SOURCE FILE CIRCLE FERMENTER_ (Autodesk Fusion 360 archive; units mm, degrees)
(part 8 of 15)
sketch "Schizzo1" plane through (-156.8, 0, 0) normal (-1, 0, 0) x axis (0, -1, 0)
  curve K1 (43.7015, -77.2094) -> (43.1419, -79.5252)
  curve K2 (45.0581, -79.5252) -> (44.4985, -77.2094)
  curve K3 (43.7015, 108.1906) -> (43.1419, 105.8748)
  curve K4 (45.0581, 105.8748) -> (44.4985, 108.1906)
  line L1 (65, 103.7507) -> (-65, 103.7507)
  curve K5 (77.2507, 91.5) -> (65, 103.7507)
  line L2 (77.2507, -63.5) -> (77.2507, 91.5)
  curve K6 (65, -75.7507) -> (77.2507, -63.5)
  line L3 (-65, -75.7507) -> (65, -75.7507)
  curve K7 (-77.2507, -63.5) -> (-65, -75.7507)
  line L4 (-77.2507, 91.5) -> (-77.2507, -63.5)
  curve K8 (-65, 103.7507) -> (-77.2507, 91.5)
  line L5 (-65, 111.4507) -> (65, 111.4507)
  curve K9 (-84.9507, 91.5) -> (-65, 111.4507)
  line L6 (-84.9507, -63.5) -> (-84.9507, 91.5)
  curve K10 (-65, -83.4507) -> (-84.9507, -63.5)
  line L7 (65, -83.4507) -> (-65, -83.4507)
  curve K11 (84.9507, -63.5) -> (65, -83.4507)
  line L8 (84.9507, 91.5) -> (84.9507, -63.5)
  curve K12 (65, 111.4507) -> (84.9507, 91.5)
  arc A1 centre (44.1, -78.7) radius 1.2645 clockwise from (45.0581, -79.5252) to (43.1419, -79.5252)
  arc A2 centre (44.1, 106.7) radius 1.2645 clockwise from (45.0581, 105.8748) to (43.1419, 105.8748)
  circle C1 centre (81.5735, 71.5) radius 1.75
  circle C2 centre (81.5735, 71.5) radius 1.75
  circle C3 centre (81.5735, -43.5) radius 1.75
  circle C4 centre (-81.5735, -43.5) radius 1.75
  circle C5 centre (-81.5735, -43.5) radius 1.75
  circle C6 centre (-81.5735, 71.5) radius 1.75
  circle C7 centre (-81.5735, 71.5) radius 1.75
  arc A3 centre (44.1, 106.7) radius 1.543 clockwise from (43.7015, 108.1906) to (44.4985, 108.1906)
  arc A4 centre (44.1, -78.7) radius 1.543 clockwise from (43.7015, -77.2094) to (44.4985, -77.2094)
extrude "Estrusione1" cut sketch "Schizzo1" profile of C1 C2 C3 C4 C5 C6 C7 against normal blind 3 named "d1008_1"
offset_faces "FacceDiOffset1" distance -0.5 named "d1010_1"
sketch "Schizzo2" plane through (0, 0, -63.5) normal (0, 0, -1) x axis (-1, 0, 0)
  line L1 (156.8, -77.2507) -> (156.8, -84.9507)
  line L2 (156.8, 84.9507) -> (156.8, 77.2507)
  line L3 (180, 88.4) -> (160, 88.4)
  line L4 (153.8, 84.9507) -> (156.8, 84.9507)
  curve K1 (160, 86.8) -> (153.8, 85.2507)
  line L5 (160, -86.8) -> (160, -88.4)
  line L6 (160, 88.4) -> (160, 86.8)
  curve K2 (160, 86.55) -> (153.9051, 85.0239)
  line L7 (153.9051, 85.0239) -> (153.8, 84.9507)
  line L8 (160, 88.4) -> (160, 86.55)
  line L9 (156.8, 77.2507) -> (153.8, 77.2507)
  curve K3 (157.8, 77.2507) -> (153.8, 77.2507)
  curve K4 (160.8, 82.6455) -> (157.8, 77.2507)
  curve K5 (164, 88.4) -> (160.8, 82.6455)
  curve K6 (168, 88.4) -> (164, 88.4)
  curve K7 (168, 88.4) -> (153.8, 77.2507)
  line L10 (156.8, 77.2507) -> (153.8, 77.2507)
  line L11 (156.8, 78.3845) -> (156.8, 77.2507)
  point P9 (153.8, 84.9507)
  point P18 (153.8, 84.9507)
  point P6 (160, 88.4)
  point P19 (160, 88.4)
  point P24 (164, 88.4)
  point P25 (168, 88.4)
  point P20 (153.8, 77.2507)
  point P26 (153.8, 77.2507)
  point P21 (156.8, 77.2507)
  point P27 (156.8, 77.2507)
  point P4 (156.8, 77.2507)
  point P28 (156.8, 77.2507)
  point P29 (156.8, 78.3845)
  point P22 (157.8, 77.2507)
  point P23 (160.8, 82.6455)
  coincident P9 P18
  coincident P6 P19
  perpendicular L3 L8
  coincident L3 P24
  coincident L3 P25
  horizontal K3
  parallel K4 K5
  coincident P20 P26
  coincident P21 P27
  coincident P4 P28
  coincident K7 P29
  coincident L2 P29
  dimension "d1011_1" = 0.25
  dimension "d1014_1" distance P20 P22 = 4
  dimension "d1015_1" distance P24 P25 = 4
  dimension "d1016_1" distance P19 P24 = 4
  dimension "d1017_1" distance P22 P24 = 11.1493
  dimension "d1018_1" distance L2 P23 = 4
sweep "Sweep1" sketch "Schizzo2" TwistAngle 0 named "d1023_1" TaperAngle 0 named "d1024_1"
sweep "Sweep2" sketch "Schizzo2" TwistAngle 0 named "d1029_1" TaperAngle 0 named "d1030_1"
remove_body "RimuoviCorpo4"
sketch "Schizzo3" plane through (-160, 0, 0) normal (-1, 0, 0) x axis (0, -1, 0)
  line L1 (-65, 116.5) -> (65, 116.5)
  curve K1 (-65, 116.5) -> (-90, 91.5)
  line L2 (-90, -63.5) -> (-90, 91.5)
  curve K2 (-65, -88.5) -> (-90, -63.5)
  line L3 (65, -88.5) -> (-65, -88.5)
  curve K3 (65, -88.5) -> (90, -63.5)
  line L4 (90, 91.5) -> (90, -63.5)
  curve K4 (65, 116.5) -> (90, 91.5)
  line L5 (65, 114.9) -> (-65, 114.9)
  curve K5 (88.4, 91.5) -> (65, 114.9)
  line L6 (88.4, -63.5) -> (88.4, 91.5)
  curve K6 (88.4, -63.5) -> (65, -86.9)
  line L7 (-65, -86.9) -> (65, -86.9)
  curve K7 (-88.4, -63.5) -> (-65, -86.9)
  line L8 (-88.4, 91.5) -> (-88.4, -63.5)
  curve K8 (-88.4, 91.5) -> (-65, 114.9)
extrude "Estrusione2" add sketch "Schizzo3" along normal blind 20 named "d1031_1"
chamfer "Smusso1" distance 0.8 named "d1033_1"
sketch "Schizzo4" plane through (-148.4, 0, 0) normal (1, 0, 0) x axis (0, 1, 0)
  curve K1 (65, 110.4651) -> (83.9651, 91.5)
  line L1 (-65, 110.4651) -> (65, 110.4651)
  curve K2 (-83.9651, 91.5) -> (-65, 110.4651)
  line L2 (-83.9651, -63.5) -> (-83.9651, 91.5)
  curve K3 (-65, -82.4651) -> (-83.9651, -63.5)
  line L3 (65, -82.4651) -> (-65, -82.4651)
  curve K4 (83.9651, -63.5) -> (65, -82.4651)
  line L4 (83.9651, 91.5) -> (83.9651, -63.5)
  curve K5 (-76.5, -63.5) -> (-65, -75)
  line L5 (-76.5, 91.5) -> (-76.5, -63.5)
  curve K6 (-65, 103) -> (-76.5, 91.5)
  line L6 (65, 103) -> (-65, 103)
  curve K7 (76.5, 91.5) -> (65, 103)
  line L7 (76.5, -63.5) -> (76.5, 91.5)
  curve K8 (65, -75) -> (76.5, -63.5)
  line L8 (-65, -75) -> (65, -75)
  circle C1 centre (-44.1, -78.7) radius 3.35
  circle C2 centre (-44.1, 106.7) radius 3.35
  circle C3 centre (-81.5735, 71.5) radius 1.75
  circle C4 centre (81.5735, 71.5) radius 1.75
  circle C5 centre (-81.5735, -43.5) radius 1.75
  circle C6 centre (81.5735, -43.5) radius 1.75
  circle C7 centre (44.1, 106.7) radius 3.35
  circle C8 centre (44.1, -78.7) radius 3.35
  circle C9 centre (0, -78.7) radius 3.35
  circle C10 centre (-80.2, 14) radius 3.35
  circle C11 centre (0, 106.7) radius 3.35
  circle C12 centre (80.2, 14) radius 3.35
extrude "Estrusione3" cut sketch "Schizzo4" profile of C3 C4 C5 C6 against normal blind 75.727 named "d1034_1"
work_plane "Piano di lavoro1" AlongDistance 3 named "d1036_1"
remove_body "RimuoviCorpo6"
work_plane "Piano di lavoro2" AlongDistance -25 named "d1050_1"
sketch "Schizzo7" plane through (0, 0, -63.5) normal (0, 0, -1) x axis (-1, 0, 0)
  line L1 (180, 88.4) -> (168, 88.4)
  curve K1 (168, 88.4) -> (156.8, 78.3845)
  curve K2 (156.8, 78.3845) -> (153.8, 77.2507)
  line L2 (180, 81.4) -> (180, 88.4)
  curve K3 (177, 81.4) -> (180, 81.4)
  curve K4 (174, 84.9) -> (177, 81.4)
  curve K5 (171, 88.4) -> (174, 84.9)
  curve K6 (168, 88.4) -> (171, 88.4)
  curve K7 (168, 88.4) -> (180, 81.4)
  point P11 (171, 88.4)
  point P3 (180, 88.4)
  point P12 (180, 88.4)
  point P8 (180, 81.4)
  point P9 (177, 81.4)
  point P5 (168, 88.4)
  point P10 (174, 84.9)
  perpendicular L1 L2
  coincident L1 P11
  horizontal K3
  parallel K4 K5
  coincident P3 P12
  dimension "d1051_1" distance P3 P8 = 7
  dimension "d1052_1" distance P8 P9 = 3
  dimension "d1053_1" distance P5 P11 = 3
  dimension "d1054_1" distance P10 K3 = 3.5 (= "d1051_1 / 2")
sketch "Schizzo6" plane through (-180, 0, 0) normal (-1, 0, 0) x axis (0, -1, 0)
  line L1 (65, 114.9) -> (-65, 114.9)
  curve K1 (88.4, 91.5) -> (65, 114.9)
  line L2 (88.4, -63.5) -> (88.4, 91.5)
  curve K2 (65, -86.9) -> (88.4, -63.5)
  line L3 (-65, -86.9) -> (65, -86.9)
  curve K3 (-88.4, -63.5) -> (-65, -86.9)
  line L4 (-88.4, 91.5) -> (-88.4, -63.5)
  curve K4 (-65, 114.9) -> (-88.4, 91.5)
  line L5 (90, 91.5) -> (90, -63.5)
  curve K5 (65, 116.5) -> (90, 91.5)
  line L6 (-65, 116.5) -> (65, 116.5)
  curve K6 (-90, 91.5) -> (-65, 116.5)
  line L7 (-90, -63.5) -> (-90, 91.5)
  curve K7 (-65, -88.5) -> (-90, -63.5)
  line L8 (65, -88.5) -> (-65, -88.5)
  curve K8 (90, -63.5) -> (65, -88.5)
  line L9 (-81.5735, 68.5) -> (-81.5735, 74.5)
  line L10 (-88.4, 60.4309) -> (-79.4522, 69.3787)
  line L11 (-88.4, 82.5691) -> (-79.4522, 73.6213)
  line L12 (-6.0795, 14) -> (-90, 14)
  line L13 (-88.4, -54.5691) -> (-79.4522, -45.6213)
  line L14 (-88.4, -32.4309) -> (-79.4522, -41.3787)
  circle C1 centre (-81.5735, -43.5) radius 1.75
  circle C2 centre (-81.5735, 71.5) radius 1.75
  arc A1 centre (-81.5735, 71.5) radius 3 clockwise from (-79.4522, 73.6213) to (-79.4522, 69.3787)
  arc A2 centre (-81.5735, -43.5) radius 3 clockwise from (-79.4522, -41.3787) to (-79.4522, -45.6213)
  point P20 (-81.5735, 71.5)
  point P24 (-88.4, 60.4309)
  point P26 (-88.4, 82.5691)
  point P27 (-90, 14)
  point P23 (-79.4522, 69.3787)
  point P32 (-79.4522, -41.3787)
  point P33 (-88.4, -32.4309)
  point P25 (-79.4522, 73.6213)
  point P29 (-79.4522, -45.6213)
  point P30 (-88.4, -54.5691)
  concentric C2 A1
  vertical L9
  coincident P20 L9
  coincident L4 P24
  coincident L4 P26
  tangent L11 A1
  tangent L10 A1
  midpoint L7 P27
  perpendicular L4 L12
  symmetric P23 L12 P32
  symmetric P24 L12 P33
  symmetric P25 L12 P29
  symmetric P26 L12 P30
  symmetric A1 L12 A2
  dimension "d1043_1" diameter A1 = 6
  dimension "d1044_1" angle L9 L10 = 135
  dimension "d1045_1" angle L9 L11 = 135
extrude "Estrusione5" add sketch "Schizzo6" profile of L4 C1 C2 A1 L10 L11 L13 A2 L14 to an object
mirror "Specchio1" mirrorStitchTolerance 0.1 named "d1049_1"
sweep "Sweep3" sketch "Schizzo7" TwistAngle 0 named "d1059_1" TaperAngle 0 named "d1060_1"
sketch "Schizzo8" plane through (-153.8, 0, 0) normal (1, 0, 0) x axis (0, 1, 0)
  line L1 (-84.9507, -63.5) -> (-84.9507, 91.5)
  curve K1 (-65, -83.4507) -> (-84.9507, -63.5)
  line L2 (65, -83.4507) -> (-65, -83.4507)
  curve K2 (84.9507, -63.5) -> (65, -83.4507)
  line L3 (84.9507, 91.5) -> (84.9507, -63.5)
  curve K3 (65, 111.4507) -> (84.9507, 91.5)
  line L4 (-65, 111.4507) -> (65, 111.4507)
  curve K4 (-84.9507, 91.5) -> (-65, 111.4507)
  curve K5 (-43.1419, 105.8748) -> (-43.7015, 108.1906)
  curve K6 (-44.4985, 108.1906) -> (-45.0581, 105.8748)
  curve K7 (-43.1419, -79.5252) -> (-43.7015, -77.2094)
  curve K8 (-44.4985, -77.2094) -> (-45.0581, -79.5252)
  line L5 (65, 103.7507) -> (-65, 103.7507)
  curve K9 (65, 103.7507) -> (77.2507, 91.5)
  line L6 (77.2507, -63.5) -> (77.2507, 91.5)
  curve K10 (77.2507, -63.5) -> (65, -75.7507)
  line L7 (-65, -75.7507) -> (65, -75.7507)
  curve K11 (-65, -75.7507) -> (-77.2507, -63.5)
  line L8 (-77.2507, 91.5) -> (-77.2507, -63.5)
  curve K12 (-77.2507, 91.5) -> (-65, 103.7507)
  circle C1 centre (-81.5735, 71.5) radius 2.25
  circle C2 centre (-81.5735, -43.5) radius 2.25
  circle C3 centre (81.5735, 71.5) radius 2.25
  circle C4 centre (81.5735, -43.5) radius 2.25
  arc A1 centre (-44.1, 106.7) radius 1.2645 clockwise from (-43.1419, 105.8748) to (-45.0581, 105.8748)
  arc A2 centre (-44.1, -78.7) radius 1.2645 clockwise from (-43.1419, -79.5252) to (-45.0581, -79.5252)
  circle C5 centre (81.5735, -43.5) radius 1.75
  circle C6 centre (81.5735, 71.5) radius 1.75
  circle C7 centre (-81.5735, 71.5) radius 1.75
  circle C8 centre (-81.5735, 71.5) radius 2.25
  circle C9 centre (-81.5735, -43.5) radius 2.25
  circle C10 centre (-81.5735, -43.5) radius 1.75
  circle C11 centre (81.5735, -43.5) radius 2.25
  circle C12 centre (81.5735, 71.5) radius 2.25
  arc A3 centre (-44.1, 106.7) radius 1.543 clockwise from (-44.4985, 108.1906) to (-43.7015, 108.1906)
  arc A4 centre (-44.1, -78.7) radius 1.543 clockwise from (-44.4985, -77.2094) to (-43.7015, -77.2094)
extrude "Estrusione6" cut sketch "Schizzo8" profile of C5 C6 C7 C10 against normal blind 84.147 named "d1061_1"
extrude "Estrusione7" add sketch "Schizzo8" profile of C1 C2 C3 C4 C5 C6 C7 C8 C9 C10 C11 C12 against normal blind 3.228 named "d1063_1"
fillet "Raccordo1" radius 3 named "d1066_1"
sketch "Schizzo1" plane through (-180, 0, 0) normal (-1, 0, 0) x axis (0, -1, 0)
  line L1 (79.4522, 73.6213) -> (80.5213, 74.6904)
  line L2 (80.5213, 68.3096) -> (79.4522, 69.3787)
  curve K1 (80.5213, 68.3096) -> (81.4, 66.1882)
  line L3 (81.4, -38.1882) -> (81.4, 66.1882)
  curve K2 (81.4, -38.1882) -> (80.5213, -40.3096)
  line L4 (79.4522, -41.3787) -> (80.5213, -40.3096)
  line L5 (80.5213, -46.6904) -> (79.4522, -45.6213)
  curve K3 (80.5213, -46.6904) -> (81.4, -48.8118)
  line L6 (81.4, -63.5) -> (81.4, -48.8118)
  curve K4 (81.4, -63.5) -> (65, -79.9)
  line L7 (-65, -79.9) -> (65, -79.9)
  curve K5 (-65, -79.9) -> (-81.4, -63.5)
  line L8 (-81.4, -48.8118) -> (-81.4, -63.5)
  curve K6 (-81.4, -48.8118) -> (-80.5213, -46.6904)
  line L9 (-79.4522, -45.6213) -> (-80.5213, -46.6904)
  line L10 (-80.5213, -40.3096) -> (-79.4522, -41.3787)
  curve K7 (-80.5213, -40.3096) -> (-81.4, -38.1882)
  line L11 (-81.4, 66.1882) -> (-81.4, -38.1882)
  curve K8 (-81.4, 66.1882) -> (-80.5213, 68.3096)
  line L12 (-79.4522, 69.3787) -> (-80.5213, 68.3096)
  line L13 (-80.5213, 74.6904) -> (-79.4522, 73.6213)
  curve K9 (-80.5213, 74.6904) -> (-81.4, 76.8118)
  line L14 (-81.4, 91.5) -> (-81.4, 76.8118)
  curve K10 (-81.4, 91.5) -> (-65, 107.9)
  line L15 (65, 107.9) -> (-65, 107.9)
  curve K11 (65, 107.9) -> (81.4, 91.5)
  line L16 (81.4, 76.8118) -> (81.4, 91.5)
  curve K12 (81.4, 76.8118) -> (80.5213, 74.6904)
  line L17 (90, 91.5) -> (90, -63.5)
  curve K13 (65, 116.5) -> (90, 91.5)
  line L18 (-65, 116.5) -> (65, 116.5)
  curve K14 (-90, 91.5) -> (-65, 116.5)
  line L19 (-90, -63.5) -> (-90, 91.5)
  curve K15 (-65, -88.5) -> (-90, -63.5)
  line L20 (65, -88.5) -> (-65, -88.5)
  curve K16 (90, -63.5) -> (65, -88.5)
  line L21 (0, -88.5) -> (0, 116.5)
  line L22 (-42.9, -25.4) -> (-42.9, 53.4)
  line L23 (36.4, -31.9) -> (-36.4, -31.9)
  line L24 (42.9, 53.4) -> (42.9, -25.4)
  line L25 (-36.4, 59.9) -> (36.4, 59.9)
  line L26 (65, -86.5) -> (-65, -86.5)
  curve K17 (88, -63.5) -> (65, -86.5)
  line L27 (88, 91.5) -> (88, -63.5)
  curve K18 (65, 114.5) -> (88, 91.5)
  line L28 (-65, 114.5) -> (65, 114.5)
  line L29 (88, 82.1691) -> (80.5213, 74.6904)
  line L30 (88, 60.8309) -> (80.5213, 68.3096)
  line L31 (88, -32.8309) -> (80.5213, -40.3096)
  line L32 (88, -54.1691) -> (80.5213, -46.6904)
  line L33 (-36.4, 59.4) -> (36.4, 59.4)
  line L34 (-42.4, -25.4) -> (-42.4, 53.4)
  line L35 (36.4, -31.4) -> (-36.4, -31.4)
  line L36 (42.4, 53.4) -> (42.4, -25.4)
  arc A1 centre (81.5735, 71.5) radius 3 clockwise from (79.4522, 69.3787) to (79.4522, 73.6213)
  arc A2 centre (81.5735, -43.5) radius 3 clockwise from (79.4522, -45.6213) to (79.4522, -41.3787)
  arc A3 centre (-81.5735, -43.5) radius 3 clockwise from (-79.4522, -41.3787) to (-79.4522, -45.6213)
  arc A4 centre (-81.5735, 71.5) radius 3 clockwise from (-79.4522, 73.6213) to (-79.4522, 69.3787)
  circle C1 centre (81.5735, -43.5) radius 1.75
  circle C2 centre (-81.5735, -43.5) radius 1.75
  circle C3 centre (-81.5735, 71.5) radius 1.75
  circle C4 centre (81.5735, 71.5) radius 1.75
  arc A5 centre (-36.4, -25.4) radius 6.5 clockwise from (-36.4, -31.9) to (-42.9, -25.4)
  arc A6 centre (36.4, -25.4) radius 6.5 clockwise from (42.9, -25.4) to (36.4, -31.9)
  arc A7 centre (36.4, 53.4) radius 6.5 clockwise from (36.4, 59.9) to (42.9, 53.4)
  arc A8 centre (-36.4, 53.4) radius 6.5 clockwise from (-42.9, 53.4) to (-36.4, 59.9)
  arc A9 centre (-36.4, 53.4) radius 6 clockwise from (-42.4, 53.4) to (-36.4, 59.4)
  arc A10 centre (-36.4, -25.4) radius 6 clockwise from (-36.4, -31.4) to (-42.4, -25.4)
  arc A11 centre (36.4, -25.4) radius 6 clockwise from (42.4, -25.4) to (36.4, -31.4)
  arc A12 centre (36.4, 53.4) radius 6 clockwise from (36.4, 59.4) to (42.4, 53.4)
  point P46 (0, 116.5)
  point P47 (0, -88.5)
  point P2 (80.5213, 74.6904)
  point P66 (80.5213, 74.6904)
  point P67 (88, 82.1691)
  point P6 (80.5213, 68.3096)
  point P68 (80.5213, 68.3096)
  point P69 (88, 60.8309)
  point P9 (80.5213, -40.3096)
  point P70 (80.5213, -40.3096)
  point P71 (88, -32.8309)
  point P13 (80.5213, -46.6904)
  point P72 (80.5213, -46.6904)
  point P73 (88, -54.1691)
  midpoint L18 P46
  midpoint L20 P47
  coincident P2 P66
  coincident L27 P67
  coincident P6 P68
  coincident L27 P69
  coincident P9 P70
  coincident L27 P71
  coincident P13 P72
  coincident L27 P73
  tangent L22 A5
  tangent L22 A8
  tangent A6 L24
  tangent A5 L23
  tangent L23 A6
  tangent A7 L25
  tangent L24 A7
  tangent L25 A8
  dimension "d1068_1" = -2
extrude "Estrusione1" new body sketch "Schizzo1" profile of L1 A1 L2 L4 A2 L5 L21 L24 L23 A6 A7 L25 K17 L26 L27 K18 L28 L29 L30 L31 L32 along normal blind 3 named "d1069_1"
fillet "Raccordo1" radius 5 named "d1072_1"
sketch "Schizzo2" plane through (-183, 0, 0) normal (-1, 0, 0) x axis (0, -1, 0)
  line L1 (79.4522, -45.6213) -> (86.5355, -52.7047)
  line L2 (86.5355, -34.2953) -> (79.4522, -41.3787)
  line L3 (88, 58.7598) -> (88, -30.7598)
  line L4 (79.4522, 69.3787) -> (86.5355, 62.2953)
  line L5 (86.5355, 80.7047) -> (79.4522, 73.6213)
  line L6 (88, 91.5) -> (88, 84.2402)
  curve K1 (65, 114.5) -> (88, 91.5)
  line L7 (0, 114.5) -> (65, 114.5)
  line L8 (0, 59.9) -> (0, 114.5)
  line L9 (36.4, 59.9) -> (0, 59.9)
  line L10 (42.9, -25.4) -> (42.9, 53.4)
  line L11 (0, -31.9) -> (36.4, -31.9)
  line L12 (0, -86.5) -> (0, -31.9)
  line L13 (65, -86.5) -> (0, -86.5)
  curve K2 (88, -63.5) -> (65, -86.5)
  line L14 (88, -56.2402) -> (88, -63.5)
  line L15 (79.4522, 73.6213) -> (80.5213, 74.6904)
  line L16 (80.5213, 68.3096) -> (79.4522, 69.3787)
  curve K3 (80.5213, 68.3096) -> (81.4, 66.1882)
  line L17 (81.4, -38.1882) -> (81.4, 66.1882)
  curve K4 (81.4, -38.1882) -> (80.5213, -40.3096)
  line L18 (79.4522, -41.3787) -> (80.5213, -40.3096)
  line L19 (80.5213, -46.6904) -> (79.4522, -45.6213)
  curve K5 (80.5213, -46.6904) -> (81.4, -48.8118)
  line L20 (81.4, -63.5) -> (81.4, -48.8118)
  curve K6 (81.4, -63.5) -> (65, -79.9)
  line L21 (-65, -79.9) -> (65, -79.9)
  curve K7 (-65, -79.9) -> (-81.4, -63.5)
  line L22 (-81.4, -48.8118) -> (-81.4, -63.5)
  curve K8 (-81.4, -48.8118) -> (-80.5213, -46.6904)
  line L23 (-79.4522, -45.6213) -> (-80.5213, -46.6904)
  line L24 (-80.5213, -40.3096) -> (-79.4522, -41.3787)
  curve K9 (-80.5213, -40.3096) -> (-81.4, -38.1882)
  line L25 (-81.4, 66.1882) -> (-81.4, -38.1882)
  curve K10 (-81.4, 66.1882) -> (-80.5213, 68.3096)
  line L26 (-79.4522, 69.3787) -> (-80.5213, 68.3096)
  line L27 (-80.5213, 74.6904) -> (-79.4522, 73.6213)
  curve K11 (-80.5213, 74.6904) -> (-81.4, 76.8118)
  line L28 (-81.4, 91.5) -> (-81.4, 76.8118)
  curve K12 (-81.4, 91.5) -> (-65, 107.9)
  line L29 (65, 107.9) -> (-65, 107.9)
  curve K13 (65, 107.9) -> (81.4, 91.5)
  line L30 (81.4, 76.8118) -> (81.4, 91.5)
  curve K14 (81.4, 76.8118) -> (80.5213, 74.6904)
  line L31 (90, 91.5) -> (90, -63.5)
  curve K15 (65, 116.5) -> (90, 91.5)
  line L32 (-65, 116.5) -> (65, 116.5)
  curve K16 (-90, 91.5) -> (-65, 116.5)
  line L33 (-90, -63.5) -> (-90, 91.5)
  curve K17 (-65, -88.5) -> (-90, -63.5)
  line L34 (65, -88.5) -> (-65, -88.5)
  curve K18 (90, -63.5) -> (65, -88.5)
  curve K19 (65, 110.9) -> (84.4, 91.5)
  line L35 (65, 110.9) -> (-65, 110.9)
  curve K20 (-84.4, 91.5) -> (-65, 110.9)
  line L36 (-84.4, 91.5) -> (-84.4, 76.8118)
  curve K21 (-82.6426, 72.5691) -> (-84.4, 76.8118)
  line L37 (-82.6426, 72.5691) -> (-81.5735, 71.5)
  line L38 (-81.5735, 71.5) -> (-82.6426, 70.4309)
  curve K22 (-84.4, 66.1882) -> (-82.6426, 70.4309)
  line L39 (-84.4, 66.1882) -> (-84.4, -38.1882)
  curve K23 (-82.6426, -42.4309) -> (-84.4, -38.1882)
  line L40 (-82.6426, -42.4309) -> (-81.5735, -43.5)
  line L41 (-81.5735, -43.5) -> (-82.6426, -44.5691)
  curve K24 (-84.4, -48.8118) -> (-82.6426, -44.5691)
  line L42 (-84.4, -48.8118) -> (-84.4, -63.5)
  curve K25 (-65, -82.9) -> (-84.4, -63.5)
  line L43 (-65, -82.9) -> (65, -82.9)
  curve K26 (84.4, -63.5) -> (65, -82.9)
  line L44 (84.4, -63.5) -> (84.4, -48.8118)
  curve K27 (82.6426, -44.5691) -> (84.4, -48.8118)
  line L45 (82.6426, -44.5691) -> (81.5735, -43.5)
  line L46 (81.5735, -43.5) -> (82.6426, -42.4309)
  curve K28 (84.4, -38.1882) -> (82.6426, -42.4309)
  line L47 (84.4, -38.1882) -> (84.4, 66.1882)
  curve K29 (82.6426, 70.4309) -> (84.4, 66.1882)
  line L48 (82.6426, 70.4309) -> (81.5735, 71.5)
  line L49 (81.5735, 71.5) -> (82.6426, 72.5691)
  curve K30 (84.4, 76.8118) -> (82.6426, 72.5691)
  line L50 (84.4, 76.8118) -> (84.4, 91.5)
  line L51 (-106.4199, 14) -> (88, 14)
  arc A1 centre (83, -56.2402) radius 5 clockwise from (86.5355, -52.7047) to (88, -56.2402)
  arc A2 centre (81.5735, -43.5) radius 3 clockwise from (79.4522, -45.6213) to (79.4522, -41.3787)
  arc A3 centre (83, -30.7598) radius 5 clockwise from (88, -30.7598) to (86.5355, -34.2953)
  arc A4 centre (83, 58.7598) radius 5 clockwise from (86.5355, 62.2953) to (88, 58.7598)
  arc A5 centre (81.5735, 71.5) radius 3 clockwise from (79.4522, 69.3787) to (79.4522, 73.6213)
  arc A6 centre (83, 84.2402) radius 5 clockwise from (88, 84.2402) to (86.5355, 80.7047)
  arc A7 centre (36.4, 53.4) radius 6.5 clockwise from (36.4, 59.9) to (42.9, 53.4)
  arc A8 centre (36.4, -25.4) radius 6.5 clockwise from (42.9, -25.4) to (36.4, -31.9)
  arc A9 centre (81.5735, 71.5) radius 3 clockwise from (79.4522, 69.3787) to (79.4522, 73.6213)
  arc A10 centre (81.5735, -43.5) radius 3 clockwise from (79.4522, -45.6213) to (79.4522, -41.3787)
  arc A11 centre (-81.5735, -43.5) radius 3 clockwise from (-79.4522, -41.3787) to (-79.4522, -45.6213)
  arc A12 centre (-81.5735, 71.5) radius 3 clockwise from (-79.4522, 73.6213) to (-79.4522, 69.3787)
  circle C1 centre (81.5735, -43.5) radius 1.75
  circle C2 centre (-81.5735, -43.5) radius 1.75
  circle C3 centre (-81.5735, 71.5) radius 1.75
  circle C4 centre (81.5735, 71.5) radius 1.75
  point P106 (25, 110.9)
  point P107 (84.4, 39)
  point P108 (88, 14)
  point P110 (25, -82.9)
  point P111 (84.4, -11)
  coincident L35 P106
  coincident L47 P107
  midpoint L3 P108
  perpendicular L47 L51
  symmetric P106 L51 P110
  symmetric P107 L51 P111
  dimension "d1073_1" = -3
  dimension "d1074_1" = 50
  dimension "d1075_1" distance L8 P106 = 25
hole "Foratura1" HoleDepth 12.597 named "d1076_1" HoleDiameter 3.5 named "d1077_1" TipAngle 180 named "d1078_1"
mirror "Specchio1" mirrorStitchTolerance 0.1 named "d1083_1"
sketch "Schizzo9" plane through (-183, 0, 0) normal (-1, 0, 0) x axis (0, -1, 0)
  line L1 (65, -86.5) -> (-65, -86.5)
  curve K1 (88, -63.5) -> (65, -86.5)
  line L2 (88, -56.2402) -> (88, -63.5)
  line L3 (79.4522, -45.6213) -> (86.5355, -52.7047)
  line L4 (86.5355, -34.2953) -> (79.4522, -41.3787)
  line L5 (88, 58.7598) -> (88, -30.7598)
  line L6 (79.4522, 69.3787) -> (86.5355, 62.2953)
  line L7 (86.5355, 80.7047) -> (79.4522, 73.6213)
  line L8 (88, 91.5) -> (88, 84.2402)
  curve K2 (65, 114.5) -> (88, 91.5)
  line L9 (-65, 114.5) -> (65, 114.5)
  curve K3 (-65, 114.5) -> (-88, 91.5)
  line L10 (-88, 84.2402) -> (-88, 91.5)
  line L11 (-79.4522, 73.6213) -> (-86.5355, 80.7047)
  line L12 (-86.5355, 62.2953) -> (-79.4522, 69.3787)
  line L13 (-88, -30.7598) -> (-88, 58.7598)
  line L14 (-79.4522, -41.3787) -> (-86.5355, -34.2953)
  line L15 (-86.5355, -52.7047) -> (-79.4522, -45.6213)
  line L16 (-88, -63.5) -> (-88, -56.2402)
  curve K4 (-88, -63.5) -> (-65, -86.5)
  line L17 (-36.4, -31.9) -> (36.4, -31.9)
  line L18 (-42.9, 53.4) -> (-42.9, -25.4)
  line L19 (36.4, 59.9) -> (-36.4, 59.9)
  line L20 (42.9, -25.4) -> (42.9, 53.4)
  arc A1 centre (83, -56.2402) radius 5 clockwise from (86.5355, -52.7047) to (88, -56.2402)
  arc A2 centre (81.5735, -43.5) radius 3 clockwise from (79.4522, -45.6213) to (79.4522, -41.3787)
  arc A3 centre (83, -30.7598) radius 5 clockwise from (88, -30.7598) to (86.5355, -34.2953)
  arc A4 centre (83, 58.7598) radius 5 clockwise from (86.5355, 62.2953) to (88, 58.7598)
  arc A5 centre (81.5735, 71.5) radius 3 clockwise from (79.4522, 69.3787) to (79.4522, 73.6213)
  arc A6 centre (83, 84.2402) radius 5 clockwise from (88, 84.2402) to (86.5355, 80.7047)
  arc A7 centre (-83, 84.2402) radius 5 clockwise from (-86.5355, 80.7047) to (-88, 84.2402)
  arc A8 centre (-81.5735, 71.5) radius 3 clockwise from (-79.4522, 73.6213) to (-79.4522, 69.3787)
  arc A9 centre (-83, 58.7598) radius 5 clockwise from (-88, 58.7598) to (-86.5355, 62.2953)
  arc A10 centre (-83, -30.7598) radius 5 clockwise from (-86.5355, -34.2953) to (-88, -30.7598)
  arc A11 centre (-81.5735, -43.5) radius 3 clockwise from (-79.4522, -41.3787) to (-79.4522, -45.6213)
  arc A12 centre (-83, -56.2402) radius 5 clockwise from (-88, -56.2402) to (-86.5355, -52.7047)
  circle C1 centre (-25, 110.9) radius 1.75
  circle C2 centre (-84.4, -11) radius 1.75
  circle C3 centre (-25, -82.9) radius 1.75
  circle C4 centre (-84.4, 39) radius 1.75
  circle C5 centre (84.4, 39) radius 1.75
  circle C6 centre (25, -82.9) radius 1.75
  circle C7 centre (84.4, -11) radius 1.75
  circle C8 centre (25, 110.9) radius 1.75
  arc A13 centre (-36.4, -25.4) radius 6.5 clockwise from (-36.4, -31.9) to (-42.9, -25.4)
  arc A14 centre (-36.4, 53.4) radius 6.5 clockwise from (-42.9, 53.4) to (-36.4, 59.9)
  arc A15 centre (36.4, 53.4) radius 6.5 clockwise from (36.4, 59.9) to (42.9, 53.4)
  arc A16 centre (36.4, -25.4) radius 6.5 clockwise from (42.9, -25.4) to (36.4, -31.9)
extrude "Estrusione8" cut sketch "Schizzo9" profile of C1 C2 C4 against normal blind 11.8105 named "d1084_1"
sketch "Schizzo7" plane through (-153.8, 0, 0) normal (-1, 0, 0) x axis (0, -1, 0)
  line L1 (20, 10.5) -> (-20, 10.5)
  line L2 (-20, -28.5) -> (20, -28.5)
  line L3 (-20, 22.5) -> (20, 22.5)
  line L4 (20, 47.5) -> (-20, 47.5)
  line L5 (-83.1107, -63.5) -> (-83.1107, -45.4967)
  curve K1 (-65, -81.6107) -> (-83.1107, -63.5)
  line L6 (65, -81.6107) -> (-65, -81.6107)
  curve K2 (83.1107, -63.5) -> (65, -81.6107)
  line L7 (83.1107, -45.4967) -> (83.1107, -63.5)
  line L8 (83.1107, 69.5033) -> (83.1107, -41.5033)
  line L9 (83.1107, 91.5) -> (83.1107, 73.4967)
  curve K3 (65, 109.6107) -> (83.1107, 91.5)
  line L10 (-65, 109.6107) -> (65, 109.6107)
  curve K4 (-83.1107, 91.5) -> (-65, 109.6107)
  line L11 (-83.1107, 73.4967) -> (-83.1107, 91.5)
  line L12 (-83.1107, -41.5033) -> (-83.1107, 69.5033)
  line L13 (0, 121.3204) -> (0, 47.5)
  line L14 (10.25, -63.8607) -> (-10.25, -63.8607)
  line L15 (10.25, -49.3607) -> (10.25, -63.8607)
  line L16 (-10.25, -49.3607) -> (10.25, -49.3607)
  line L17 (-10.25, -63.8607) -> (-10.25, -49.3607)
  line L18 (10.25, -49.3607) -> (-10.25, -63.8607)
  line L19 (-10.25, -49.3607) -> (10.25, -63.8607)
  arc A1 centre (-20, 35) radius 12.5 clockwise from (-20, 22.5) to (-20, 47.5)
  arc A2 centre (20, 35) radius 12.5 clockwise from (20, 47.5) to (20, 22.5)
  circle C1 centre (44.1, -78.7) radius 1.75
  circle C2 centre (44.1, 106.7) radius 1.75
  arc A3 centre (-82.6107, -41.5033) radius 0.5 clockwise from (-82.3802, -41.947) to (-83.1107, -41.5033)
  arc A4 centre (-81.5735, -43.5) radius 1.75 clockwise from (-82.3802, -41.947) to (-82.3802, -45.053)
  arc A5 centre (-82.6107, -45.4967) radius 0.5 clockwise from (-83.1107, -45.4967) to (-82.3802, -45.053)
  arc A6 centre (82.6107, -45.4967) radius 0.5 clockwise from (82.3802, -45.053) to (83.1107, -45.4967)
  arc A7 centre (81.5735, -43.5) radius 1.75 clockwise from (82.3802, -45.053) to (82.3802, -41.947)
  arc A8 centre (82.6107, -41.5033) radius 0.5 clockwise from (83.1107, -41.5033) to (82.3802, -41.947)
  arc A9 centre (82.6107, 69.5033) radius 0.5 clockwise from (82.3802, 69.947) to (83.1107, 69.5033)
  arc A10 centre (81.5735, 71.5) radius 1.75 clockwise from (82.3802, 69.947) to (82.3802, 73.053)
  arc A11 centre (82.6107, 73.4967) radius 0.5 clockwise from (83.1107, 73.4967) to (82.3802, 73.053)
  arc A12 centre (-82.6107, 73.4967) radius 0.5 clockwise from (-82.3802, 73.053) to (-83.1107, 73.4967)
  arc A13 centre (-81.5735, 71.5) radius 1.75 clockwise from (-82.3802, 73.053) to (-82.3802, 69.947)
  arc A14 centre (-82.6107, 69.5033) radius 0.5 clockwise from (-83.1107, 69.5033) to (-82.3802, 69.947)
  arc A15 centre (-20, -9) radius 19.5 clockwise from (-20, -28.5) to (-20, 10.5)
  arc A16 centre (20, -9) radius 19.5 clockwise from (20, 10.5) to (20, -28.5)
  circle C3 centre (-44.1, 106.7) radius 1.75
  circle C4 centre (-44.1, -78.7) radius 1.75
  circle C5 centre (0, -78.7) radius 1.75
  circle C6 centre (80.2, 14) radius 1.75
  circle C7 centre (0, 106.7) radius 1.75
  circle C8 centre (-80.2, 14) radius 1.75
  point P50 (0, 47.5)
  point P56 (0, -56.6107)
  point P54 (10.25, -49.3607)
  point P55 (-10.25, -49.3607)
  point P53 (10.25, -63.8607)
  midpoint L4 P50
  horizontal L14
  perpendicular L14 L15
  parallel L14 L16
  parallel L15 L17
  coincident L18 P56
  coincident L19 P56
  coincident L13 P56
  vertical L13
  dimension "d1086_1" distance P54 P55 = 20.5
  dimension "d1087_1" distance P53 P54 = 14.5
  dimension "d1102_1" distance L6 P56 = 25
extrude "Estrusione2" cut sketch "Schizzo7" profile of L14 L15 L16 L17 against normal blind 7.886 named "d1089_1"
component_insert "Inserimento componente2"
joint "Assembla4" alignAngle 0 named "d1095_1" alignOffsetX 0 named "d1096_1" alignOffsetY 0 named "d1097_1" alignOffsetZ 0.25 named "d1098_1"
sketch "Schizzo8" plane through (-153.8, 0, 0) normal (-1, 0, 0) x axis (0, -1, 0)
  line L1 (-10.25, -63.8607) -> (10.25, -63.8607)
  line L2 (10.25, -49.3607) -> (-10.25, -49.3607)
  line L3 (10.25, -63.8607) -> (10.25, -49.3607)
  line L4 (20, 10.5) -> (-20, 10.5)
  line L5 (-20, -28.5) -> (20, -28.5)
  line L6 (-20, 22.5) -> (20, 22.5)
  line L7 (20, 47.5) -> (-20, 47.5)
  line L8 (-83.1107, -63.5) -> (-83.1107, -45.4967)
  curve K1 (-65, -81.6107) -> (-83.1107, -63.5)
  line L9 (65, -81.6107) -> (-65, -81.6107)
  curve K2 (83.1107, -63.5) -> (65, -81.6107)
  line L10 (83.1107, -45.4967) -> (83.1107, -63.5)
  line L11 (83.1107, 69.5033) -> (83.1107, -41.5033)
  line L12 (83.1107, 91.5) -> (83.1107, 73.4967)
  curve K3 (65, 109.6107) -> (83.1107, 91.5)
  line L13 (-65, 109.6107) -> (65, 109.6107)
  curve K4 (-83.1107, 91.5) -> (-65, 109.6107)
  line L14 (-83.1107, 73.4967) -> (-83.1107, 91.5)
  line L15 (-83.1107, -41.5033) -> (-83.1107, 69.5033)
  line L16 (-10.25, -49.3607) -> (-10.25, -63.8607)
  arc A1 centre (-20, 35) radius 12.5 clockwise from (-20, 22.5) to (-20, 47.5)
  arc A2 centre (20, 35) radius 12.5 clockwise from (20, 47.5) to (20, 22.5)
  circle C1 centre (-44.1, -78.7) radius 1.75
  circle C2 centre (44.1, 106.7) radius 1.75
  arc A3 centre (-82.6107, -41.5033) radius 0.5 clockwise from (-82.3802, -41.947) to (-83.1107, -41.5033)
  arc A4 centre (-81.5735, -43.5) radius 1.75 clockwise from (-82.3802, -41.947) to (-82.3802, -45.053)
  arc A5 centre (-82.6107, -45.4967) radius 0.5 clockwise from (-83.1107, -45.4967) to (-82.3802, -45.053)
  arc A6 centre (82.6107, -45.4967) radius 0.5 clockwise from (82.3802, -45.053) to (83.1107, -45.4967)
  arc A7 centre (81.5735, -43.5) radius 1.75 clockwise from (82.3802, -45.053) to (82.3802, -41.947)
  arc A8 centre (82.6107, -41.5033) radius 0.5 clockwise from (83.1107, -41.5033) to (82.3802, -41.947)
  arc A9 centre (82.6107, 69.5033) radius 0.5 clockwise from (82.3802, 69.947) to (83.1107, 69.5033)
  arc A10 centre (81.5735, 71.5) radius 1.75 clockwise from (82.3802, 69.947) to (82.3802, 73.053)
  arc A11 centre (82.6107, 73.4967) radius 0.5 clockwise from (83.1107, 73.4967) to (82.3802, 73.053)
  arc A12 centre (-82.6107, 73.4967) radius 0.5 clockwise from (-82.3802, 73.053) to (-83.1107, 73.4967)
  arc A13 centre (-81.5735, 71.5) radius 1.75 clockwise from (-82.3802, 73.053) to (-82.3802, 69.947)
  arc A14 centre (-82.6107, 69.5033) radius 0.5 clockwise from (-83.1107, 69.5033) to (-82.3802, 69.947)
  circle C3 centre (-12.35, -56.6107) radius 1.55
  circle C4 centre (-12.35, -56.6107) radius 1.75
  circle C5 centre (-44.1, 106.7) radius 1.75
  circle C6 centre (44.1, -78.7) radius 1.75
  arc A15 centre (-20, -9) radius 19.5 clockwise from (-20, -28.5) to (-20, 10.5)
  arc A16 centre (20, -9) radius 19.5 clockwise from (20, 10.5) to (20, -28.5)
  circle C7 centre (0, -78.7) radius 1.75
  circle C8 centre (80.2, 14) radius 1.75
  circle C9 centre (0, 106.7) radius 1.75
  circle C10 centre (-80.2, 14) radius 1.75
  concentric C3 C4
  dimension "d1099_1" diameter C4 = 3.5
extrude "Estrusione3" cut sketch "Schizzo8" profile of C4 against normal blind 3 named "d1100_1"
sketch "Schizzo3" plane through (-183, 0, 0) normal (-1, 0, 0) x axis (0, -1, 0)
  line L1 (65, -86.5) -> (-65, -86.5)
  curve K1 (88, -63.5) -> (65, -86.5)
  line L2 (88, -56.2402) -> (88, -63.5)
  line L3 (79.4522, -45.6213) -> (86.5355, -52.7047)
  line L4 (86.5355, -34.2953) -> (79.4522, -41.3787)
  line L5 (88, 58.7598) -> (88, -30.7598)
  line L6 (79.4522, 69.3787) -> (86.5355, 62.2953)
  line L7 (86.5355, 80.7047) -> (79.4522, 73.6213)
  line L8 (88, 91.5) -> (88, 84.2402)
  curve K2 (65, 114.5) -> (88, 91.5)
  line L9 (-65, 114.5) -> (65, 114.5)
  curve K3 (-65, 114.5) -> (-88, 91.5)
  line L10 (-88, 84.2402) -> (-88, 91.5)
  line L11 (-79.4522, 73.6213) -> (-86.5355, 80.7047)
  line L12 (-86.5355, 62.2953) -> (-79.4522, 69.3787)
  line L13 (-88, -30.7598) -> (-88, 58.7598)
  line L14 (-79.4522, -41.3787) -> (-86.5355, -34.2953)
  line L15 (-86.5355, -52.7047) -> (-79.4522, -45.6213)
  line L16 (-88, -63.5) -> (-88, -56.2402)
  curve K4 (-88, -63.5) -> (-65, -86.5)
  line L17 (-36.4, -31.9) -> (36.4, -31.9)
  line L18 (-42.9, 53.4) -> (-42.9, -25.4)
  line L19 (36.4, 59.9) -> (-36.4, 59.9)
  line L20 (42.9, -25.4) -> (42.9, 53.4)
  line L21 (-42.9, 14) -> (42.9, 14)
  line L22 (0, -31.9) -> (0, 59.9)
  arc A1 centre (83, -56.2402) radius 5 clockwise from (86.5355, -52.7047) to (88, -56.2402)
  arc A2 centre (81.5735, -43.5) radius 3 clockwise from (79.4522, -45.6213) to (79.4522, -41.3787)
  arc A3 centre (83, -30.7598) radius 5 clockwise from (88, -30.7598) to (86.5355, -34.2953)
  arc A4 centre (83, 58.7598) radius 5 clockwise from (86.5355, 62.2953) to (88, 58.7598)
  arc A5 centre (81.5735, 71.5) radius 3 clockwise from (79.4522, 69.3787) to (79.4522, 73.6213)
  arc A6 centre (83, 84.2402) radius 5 clockwise from (88, 84.2402) to (86.5355, 80.7047)
  arc A7 centre (-83, 84.2402) radius 5 clockwise from (-86.5355, 80.7047) to (-88, 84.2402)
  arc A8 centre (-81.5735, 71.5) radius 3 clockwise from (-79.4522, 73.6213) to (-79.4522, 69.3787)
  arc A9 centre (-83, 58.7598) radius 5 clockwise from (-88, 58.7598) to (-86.5355, 62.2953)
  arc A10 centre (-83, -30.7598) radius 5 clockwise from (-86.5355, -34.2953) to (-88, -30.7598)
  arc A11 centre (-81.5735, -43.5) radius 3 clockwise from (-79.4522, -41.3787) to (-79.4522, -45.6213)
  arc A12 centre (-83, -56.2402) radius 5 clockwise from (-88, -56.2402) to (-86.5355, -52.7047)
  circle C1 centre (-25, 110.9) radius 1.75
  circle C2 centre (-84.4, -11) radius 1.75
  circle C3 centre (-25, -82.9) radius 1.75
  circle C4 centre (-84.4, 39) radius 1.75
  circle C5 centre (84.4, 39) radius 1.75
  circle C6 centre (25, -82.9) radius 1.75
  circle C7 centre (84.4, -11) radius 1.75
  circle C8 centre (25, 110.9) radius 1.75
  arc A13 centre (-36.4, -25.4) radius 6.5 clockwise from (-36.4, -31.9) to (-42.9, -25.4)
  arc A14 centre (-36.4, 53.4) radius 6.5 clockwise from (-42.9, 53.4) to (-36.4, 59.9)
  arc A15 centre (36.4, 53.4) radius 6.5 clockwise from (36.4, 59.9) to (42.9, 53.4)
  arc A16 centre (36.4, -25.4) radius 6.5 clockwise from (42.9, -25.4) to (36.4, -31.9)
  circle C9 centre (0, 14) radius 70
  circle C10 centre (0, 14) radius 78
  point P66 (42.9, 14)
  point P67 (-42.9, 14)
  point P68 (0, 59.9)
  point P69 (0, -31.9)
  point P70 (0, 14)
  midpoint L20 P66
  midpoint L18 P67
  midpoint L19 P68
  midpoint L17 P69
  midpoint L21 P70
  dimension "d1103_1" diameter C9 = 140
  dimension "d1104_1" = 8
extrude "Estrusione1" sketch "Schizzo3" profile of C9 C10 blind -15 named "d1106_1"
sketch "Schizzo1" plane through (-165, 0, 0) normal (1, 0, 0) x axis (0, 1, 0)
  line L1 (106.358, 14) -> (0, 14)
  line L2 (0, 100.4601) -> (0, 14)
  circle C1 centre (0, 14) radius 70
  circle C2 centre (0, 14) radius 78
  circle C3 centre (0, 14) radius 74
  circle C4 centre (0, 14) radius 74.2
  circle C5 centre (0, 14) radius 73.8
  circle C6 centre (70, 14) radius 4
  circle C7 centre (0, 14) radius 71.6
  circle C8 centre (63.0678, 44.3719) radius 4
  circle C9 centre (43.6443, 68.7282) radius 4
  circle C10 centre (15.5765, 82.245) radius 4
  circle C11 centre (-15.5765, 82.245) radius 4
  circle C12 centre (-43.6443, 68.7282) radius 4
  circle C13 centre (-63.0678, 44.3719) radius 4
  circle C14 centre (-70, 14) radius 4
  circle C15 centre (-63.0678, -16.3719) radius 4
  circle C16 centre (-43.6443, -40.7282) radius 4
  circle C17 centre (-15.5765, -54.245) radius 4
  circle C18 centre (15.5765, -54.245) radius 4
  circle C19 centre (43.6443, -40.7282) radius 4
  circle C20 centre (63.0678, -16.3719) radius 4
  point P2 (0, 14)
  point P4 (0, 14)
  point P6 (0, 14)
  point P10 (70, 14)
  concentric C1 C3
  coincident P2 P4
  horizontal L1
  coincident P2 P6
  perpendicular L1 L2
  coincident C1 P10
  coincident L1 P10
  tangent C3 C6
  dimension "d1108_1" diameter C3 = 148
  dimension "d1109_1" = 0.2
  dimension "d1110_1" = -0.2
  dimension "d1111_1" = 1.6
  dimension "d1113_1" C-Pattern1-Angle = 360
extrude "Estrusione2" cut sketch "Schizzo1" profile of C2 C6 C7 C8 C9 C10 C11 C12 C13 C14 C15 C16 C17 C18 C19 C20 against normal blind 12 named "d1114_1"
sketch "Schizzo2" plane through (-177, 0, 0) normal (1, 0, 0) x axis (0, 1, 0)
  line L1 (114.4184, 14) -> (0, 14)
  line L2 (63.0678, -16.3719) -> (0, 14)
  line L3 (69.8048, -1.9325) -> (0, 14)
  line L4 (96.3087, -7.9818) -> (69.8048, -1.9325)
  line L5 (74.9357, -7.6481) -> (70.9793, -3.9772)
  line L6 (76.9075, 0.9909) -> (71.7501, -0.5999)
  line L7 (74.9357, 35.6481) -> (70.9793, 31.9772)
  line L8 (76.9075, 27.0091) -> (71.7501, 28.5999)
  line L9 (58.1219, 66.0177) -> (56.1501, 60.9936)
  line L10 (63.6468, 59.0897) -> (58.31, 58.2853)
  line L11 (29.7964, 86.0845) -> (30.1998, 80.7024)
  line L12 (37.7801, 82.2397) -> (33.3208, 79.1994)
  line L13 (-4.4306, 91.8741) -> (-1.7321, 87.2)
  line L14 (4.4306, 91.8741) -> (1.7321, 87.2)
  line L15 (-37.7801, 82.2397) -> (-33.3208, 79.1994)
  line L16 (-29.7964, 86.0845) -> (-30.1998, 80.7024)
  line L17 (-63.6468, 59.0897) -> (-58.31, 58.2853)
  line L18 (-58.1219, 66.0177) -> (-56.1501, 60.9936)
  line L19 (-76.9075, 27.0091) -> (-71.7501, 28.5999)
  line L20 (-74.9357, 35.6481) -> (-70.9793, 31.9772)
  line L21 (-74.9357, -7.6481) -> (-70.9793, -3.9772)
  line L22 (-76.9075, 0.9909) -> (-71.7501, -0.5999)
  line L23 (-58.1219, -38.0177) -> (-56.1501, -32.9936)
  line L24 (-63.6468, -31.0897) -> (-58.31, -30.2853)
  line L25 (-29.7964, -58.0845) -> (-30.1998, -52.7024)
  line L26 (-37.7801, -54.2397) -> (-33.3208, -51.1994)
  line L27 (4.4306, -63.8741) -> (1.7321, -59.2)
  line L28 (-4.4306, -63.8741) -> (-1.7321, -59.2)
  line L29 (37.7801, -54.2397) -> (33.3208, -51.1994)
  line L30 (29.7964, -58.0845) -> (30.1998, -52.7024)
  line L31 (63.6468, -31.0897) -> (58.31, -30.2853)
  line L32 (58.1219, -38.0177) -> (56.1501, -32.9936)
  arc A1 centre (63.0678, -16.3719) radius 4 clockwise from (66.0311, -13.685) to (62.8147, -20.3638)
  arc A2 centre (0, 14) radius 71.6 clockwise from (62.8147, -20.3638) to (47.4799, -39.5931)
  arc A3 centre (43.6443, -40.7282) radius 4 clockwise from (47.4799, -39.5931) to (41.6842, -44.215)
  arc A4 centre (0, 14) radius 71.6 clockwise from (41.6842, -44.215) to (19.5247, -54.8865)
  arc A5 centre (15.5765, -54.245) radius 4 clockwise from (19.5247, -54.8865) to (12.2976, -56.536)
  arc A6 centre (0, 14) radius 71.6 clockwise from (12.2976, -56.536) to (-12.2976, -56.536)
  arc A7 centre (-15.5765, -54.245) radius 4 clockwise from (-12.2976, -56.536) to (-19.5247, -54.8865)
  arc A8 centre (0, 14) radius 71.6 clockwise from (-19.5247, -54.8865) to (-41.6842, -44.215)
  arc A9 centre (-43.6443, -40.7282) radius 4 clockwise from (-41.6842, -44.215) to (-47.4799, -39.5931)
  arc A10 centre (0, 14) radius 71.6 clockwise from (-47.4799, -39.5931) to (-62.8147, -20.3638)
  arc A11 centre (-63.0678, -16.3719) radius 4 clockwise from (-62.8147, -20.3638) to (-66.0311, -13.685)
  arc A12 centre (0, 14) radius 71.6 clockwise from (-66.0311, -13.685) to (-71.504, 10.2935)
  arc A13 centre (-70, 14) radius 4 clockwise from (-71.504, 10.2935) to (-71.504, 17.7065)
  arc A14 centre (0, 14) radius 71.6 clockwise from (-71.504, 17.7065) to (-66.0311, 41.685)
  arc A15 centre (-63.0678, 44.3719) radius 4 clockwise from (-66.0311, 41.685) to (-62.8147, 48.3638)
  arc A16 centre (0, 14) radius 71.6 clockwise from (-62.8147, 48.3638) to (-47.4799, 67.5931)
  arc A17 centre (-43.6443, 68.7282) radius 4 clockwise from (-47.4799, 67.5931) to (-41.6842, 72.215)
  arc A18 centre (0, 14) radius 71.6 clockwise from (-41.6842, 72.215) to (-19.5247, 82.8865)
  arc A19 centre (-15.5765, 82.245) radius 4 clockwise from (-19.5247, 82.8865) to (-12.2976, 84.536)
  arc A20 centre (0, 14) radius 71.6 clockwise from (-12.2976, 84.536) to (12.2976, 84.536)
  arc A21 centre (15.5765, 82.245) radius 4 clockwise from (12.2976, 84.536) to (19.5247, 82.8865)
  arc A22 centre (0, 14) radius 71.6 clockwise from (19.5247, 82.8865) to (41.6842, 72.215)
  arc A23 centre (43.6443, 68.7282) radius 4 clockwise from (41.6842, 72.215) to (47.4799, 67.5931)
  arc A24 centre (0, 14) radius 71.6 clockwise from (47.4799, 67.5931) to (62.8147, 48.3638)
  arc A25 centre (63.0678, 44.3719) radius 4 clockwise from (62.8147, 48.3638) to (66.0311, 41.685)
  arc A26 centre (0, 14) radius 71.6 clockwise from (66.0311, 41.685) to (71.504, 17.7065)
  arc A27 centre (70, 14) radius 4 clockwise from (71.504, 17.7065) to (71.504, 10.2935)
  arc A28 centre (0, 14) radius 71.6 clockwise from (71.504, 10.2935) to (66.0311, -13.685)
  circle C1 centre (0, 14) radius 78
  arc A29 centre (0, 14) radius 71.6 clockwise from (62.8147, -20.3638) to (47.4799, -39.5931)
  arc A30 centre (63.0678, -16.3719) radius 4 clockwise from (66.0311, -13.685) to (62.8147, -20.3638)
  arc A31 centre (0, 14) radius 71.6 clockwise from (71.504, 10.2935) to (66.0311, -13.685)
  arc A32 centre (70, 14) radius 4 clockwise from (71.504, 17.7065) to (71.504, 10.2935)
  arc A33 centre (0, 14) radius 71.6 clockwise from (66.0311, 41.685) to (71.504, 17.7065)
  arc A34 centre (63.0678, 44.3719) radius 4 clockwise from (62.8147, 48.3638) to (66.0311, 41.685)
  arc A35 centre (0, 14) radius 71.6 clockwise from (47.4799, 67.5931) to (62.8147, 48.3638)
  arc A36 centre (43.6443, 68.7282) radius 4 clockwise from (41.6842, 72.215) to (47.4799, 67.5931)
  arc A37 centre (0, 14) radius 71.6 clockwise from (19.5247, 82.8865) to (41.6842, 72.215)
  arc A38 centre (15.5765, 82.245) radius 4 clockwise from (12.2976, 84.536) to (19.5247, 82.8865)
  arc A39 centre (0, 14) radius 71.6 clockwise from (-12.2976, 84.536) to (12.2976, 84.536)
  arc A40 centre (-15.5765, 82.245) radius 4 clockwise from (-19.5247, 82.8865) to (-12.2976, 84.536)
  arc A41 centre (0, 14) radius 71.6 clockwise from (-41.6842, 72.215) to (-19.5247, 82.8865)
  arc A42 centre (-43.6443, 68.7282) radius 4 clockwise from (-47.4799, 67.5931) to (-41.6842, 72.215)
  arc A43 centre (0, 14) radius 71.6 clockwise from (-62.8147, 48.3638) to (-47.4799, 67.5931)
  arc A44 centre (-63.0678, 44.3719) radius 4 clockwise from (-66.0311, 41.685) to (-62.8147, 48.3638)
  arc A45 centre (0, 14) radius 71.6 clockwise from (-71.504, 17.7065) to (-66.0311, 41.685)
  arc A46 centre (-70, 14) radius 4 clockwise from (-71.504, 10.2935) to (-71.504, 17.7065)
  arc A47 centre (0, 14) radius 71.6 clockwise from (-66.0311, -13.685) to (-71.504, 10.2935)
  arc A48 centre (-63.0678, -16.3719) radius 4 clockwise from (-62.8147, -20.3638) to (-66.0311, -13.685)
  arc A49 centre (0, 14) radius 71.6 clockwise from (-47.4799, -39.5931) to (-62.8147, -20.3638)
  arc A50 centre (-43.6443, -40.7282) radius 4 clockwise from (-41.6842, -44.215) to (-47.4799, -39.5931)
  arc A51 centre (0, 14) radius 71.6 clockwise from (-19.5247, -54.8865) to (-41.6842, -44.215)
  arc A52 centre (-15.5765, -54.245) radius 4 clockwise from (-12.2976, -56.536) to (-19.5247, -54.8865)
  arc A53 centre (0, 14) radius 71.6 clockwise from (12.2976, -56.536) to (-12.2976, -56.536)
  arc A54 centre (15.5765, -54.245) radius 4 clockwise from (19.5247, -54.8865) to (12.2976, -56.536)
  arc A55 centre (0, 14) radius 71.6 clockwise from (41.6842, -44.215) to (19.5247, -54.8865)
  arc A56 centre (43.6443, -40.7282) radius 4 clockwise from (47.4799, -39.5931) to (41.6842, -44.215)
  circle C2 centre (0, 14) radius 70
  arc A57 centre (0, 14) radius 72.2 clockwise from (72.1032, 10.2625) to (66.5844, -13.917)
  arc A58 centre (72.3397, -2.5111) radius 2 clockwise from (70.9793, -3.9772) to (71.7501, -0.5999)
  arc A59 centre (72.3397, 30.5111) radius 2 clockwise from (71.7501, 28.5999) to (70.9793, 31.9772)
  arc A60 centre (58.0119, 60.2629) radius 2 clockwise from (58.31, 58.2853) to (56.1501, 60.9936)
  arc A61 centre (32.1942, 80.8519) radius 2 clockwise from (33.3208, 79.1994) to (30.1998, 80.7024)
  arc A62 centre (0, 88.2) radius 2 clockwise from (1.7321, 87.2) to (-1.7321, 87.2)
  arc A63 centre (-32.1942, 80.8519) radius 2 clockwise from (-30.1998, 80.7024) to (-33.3208, 79.1994)
  arc A64 centre (-58.0119, 60.2629) radius 2 clockwise from (-56.1501, 60.9936) to (-58.31, 58.2853)
  arc A65 centre (-72.3397, 30.5111) radius 2 clockwise from (-70.9793, 31.9772) to (-71.7501, 28.5999)
  arc A66 centre (-72.3397, -2.5111) radius 2 clockwise from (-71.7501, -0.5999) to (-70.9793, -3.9772)
  arc A67 centre (-58.0119, -32.2629) radius 2 clockwise from (-58.31, -30.2853) to (-56.1501, -32.9936)
  arc A68 centre (-32.1942, -52.8519) radius 2 clockwise from (-33.3208, -51.1994) to (-30.1998, -52.7024)
  arc A69 centre (0, -60.2) radius 2 clockwise from (-1.7321, -59.2) to (1.7321, -59.2)
  arc A70 centre (32.1942, -52.8519) radius 2 clockwise from (30.1998, -52.7024) to (33.3208, -51.1994)
  arc A71 centre (58.0119, -32.2629) radius 2 clockwise from (56.1501, -32.9936) to (58.31, -30.2853)
  point P6 (0, 14)
  point P88 (0, 14)
  point P90 (0, 14)
  point P4 (63.0678, -16.3719)
  point P91 (63.0678, -16.3719)
  point P92 (0, 14)
  point P93 (69.8048, -1.9325)
  point P98 (72.3397, -2.5111)
  point P100 (74.9357, -7.6481)
  point P99 (70.9793, -3.9772)
  point P101 (71.7501, -0.5999)
  point P102 (76.9075, 0.9909)
  coincident P6 P88
  horizontal L1
  coincident P6 P90
  coincident P4 P91
  coincident P6 P92
  midpoint A28 P93
  parallel L3 L4
  coincident L4 P98
  tangent A57 A58
  coincident C1 P100
  tangent L5 A58
  symmetric L4 P99 P101
  symmetric L4 P100 P102
  dimension "d1116_1" = 0.6
  dimension "d1117_1" diameter A58 = 4
  dimension "d1118_1" angle L4 L5 = 30
  dimension "d1120_1" C-Pattern1-Angle = 360
extrude "Estrusione3" add sketch "Schizzo2" profile of C1 A58 L5 L6 L7 A59 L8 L9 A60 L10 L11 A61 L12 L13 A62 L14 L15 A63 L16 L17 A64 L18 L19 A65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 along normal blind 12 named "d1121_1"
fillet "Raccordo1" radius 1 named "d1124_1"
sketch "Schizzo3" plane through (-180, 0, 0) normal (-1, 0, 0) x axis (0, -1, 0)
  line L1 (-70, 14) -> (70, 14)
  line L2 (69.3077, 4.1796) -> (61.1321, 9.9042)
  line L3 (70.7767, 9.9042) -> (61.1321, 9.9042)
  line L4 (69.3077, 23.8204) -> (61.1321, 18.0958)
  line L5 (-43.1586, 69.1121) -> (-34.1131, 64.8941)
  line L6 (-26.1492, 78.9324) -> (-27.019, 68.9898)
  line L7 (-26.1492, -50.9324) -> (-27.019, -40.9898)
  line L8 (-43.1586, -41.1121) -> (-34.1131, -36.8941)
  circle C1 centre (0, 14) radius 70
  circle C2 centre (0, 14) radius 78
  circle C3 centre (0, 14) radius 70
  arc A1 centre (64, 14) radius 5 clockwise from (66.8679, 9.9042) to (61.1321, 18.0958)
  arc A2 centre (-32, 69.4256) radius 5 clockwise from (-29.8869, 73.9572) to (-34.1131, 64.8941)
  arc A3 centre (-32, -41.4256) radius 5 clockwise from (-36.981, -41.8614) to (-27.019, -40.9898)
  point P4 (70, 14)
  point P5 (-70, 14)
  point P3 (0, 14)
  point P6 (64, 14)
  point P7 (61.1321, 9.9042)
  point P10 (61.1321, 18.0958)
  point P8 (69.3077, 4.1796)
  point P11 (69.3077, 23.8204)
  point P12 (66.8679, 9.9042)
  coincident C3 P4
  coincident C3 P5
  horizontal L1
  coincident P3 L1
  coincident L1 P6
  horizontal L3
  coincident P7 A1
  tangent L2 A1
  symmetric L1 P7 P10
  symmetric L1 P8 P11
  coincident L3 P12
  coincident C3 P11
  dimension "d1125_1" diameter A1 = 10
  dimension "d1126_1" distance P4 P6 = 6
  dimension "d1127_1" angle L2 L3 = 35
  dimension "d1129_1" C-Pattern1-Angle = 360
extrude "Estrusione4" add sketch "Schizzo3" profile of C1 C3 A1 L2 L4 L5 A2 L6 L7 A3 L8 against normal blind 15 named "d1130_1"
sketch "Schizzo4" plane through (-180, 0, 0) normal (-1, 0, 0) x axis (0, -1, 0)
  line L1 (61.1321, 18.0958) -> (69.3077, 23.8204)
  line L2 (69.3077, 4.1796) -> (61.1321, 9.9042)
  line L3 (-27.019, -40.9898) -> (-26.1492, -50.9324)
  line L4 (-43.1586, -41.1121) -> (-34.1131, -36.8941)
  line L5 (-34.1131, 64.8941) -> (-43.1586, 69.1121)
  line L6 (-26.1492, 78.9324) -> (-27.019, 68.9898)
  arc A1 centre (0, 14) radius 70 clockwise from (-26.1492, 78.9324) to (69.3077, 23.8204)
  arc A2 centre (64, 14) radius 5 clockwise from (61.1321, 9.9042) to (61.1321, 18.0958)
  arc A3 centre (0, 14) radius 70 clockwise from (69.3077, 4.1796) to (-26.1492, -50.9324)
  arc A4 centre (-32, -41.4256) radius 5 clockwise from (-34.1131, -36.8941) to (-27.019, -40.9898)
  arc A5 centre (0, 14) radius 70 clockwise from (-43.1586, -41.1121) to (-43.1586, 69.1121)
  arc A6 centre (-32, 69.4256) radius 5 clockwise from (-27.019, 68.9898) to (-34.1131, 64.8941)
  circle C1 centre (0, 14) radius 78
